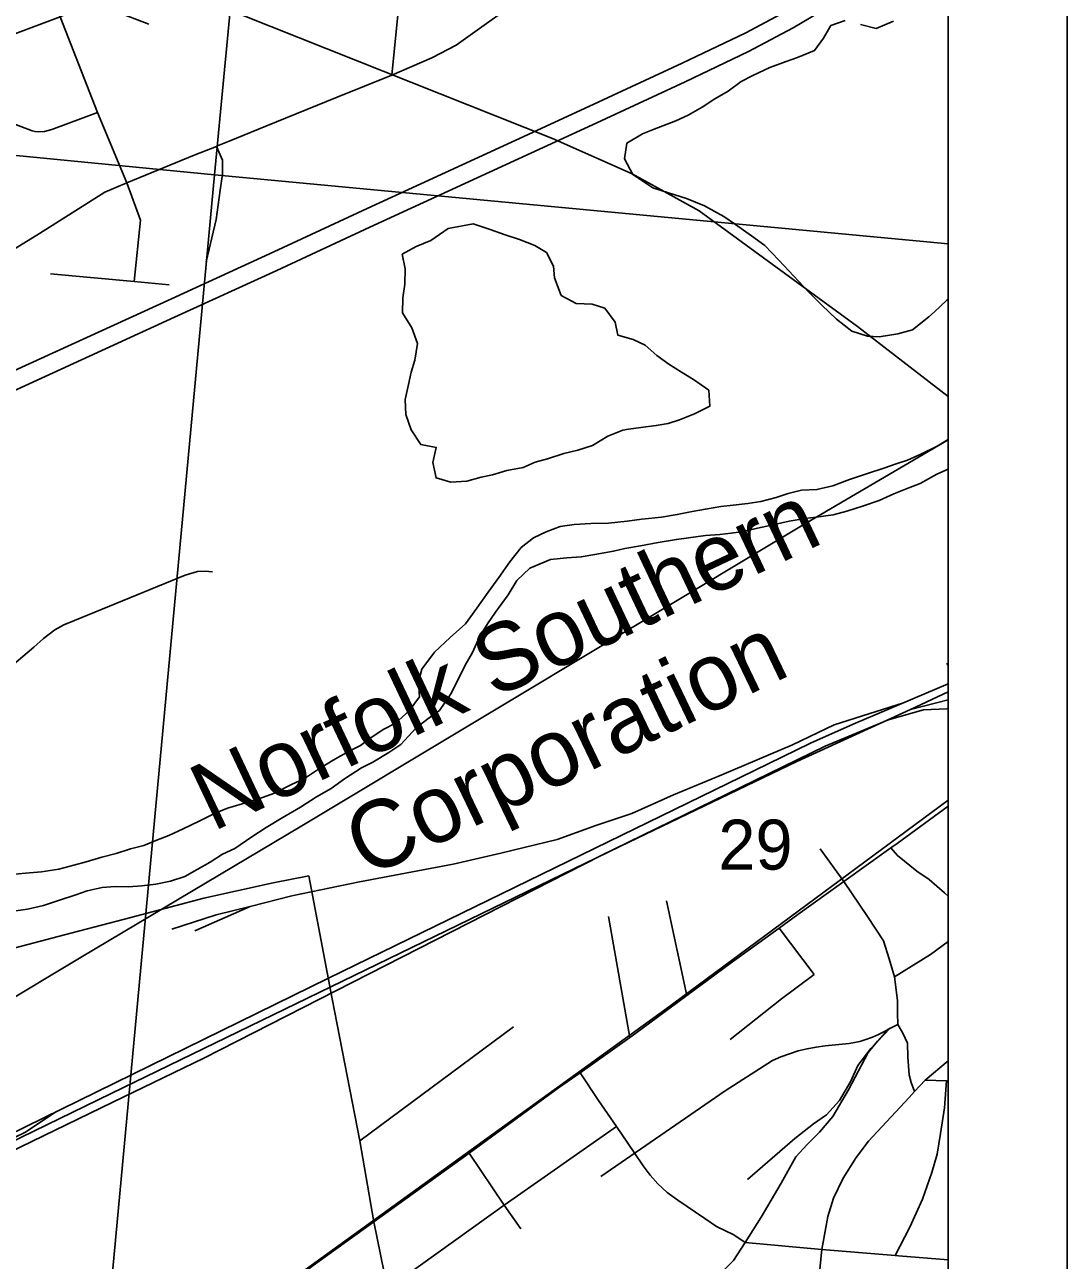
# Model space of a CAD drawing. Extents: x 0 to 34, y 0 to 22.
# Drawn here: x 8.126 to 9, y 18.996 to 20.032 of the extents above; entities that cross this region are included whole.
import ezdxf

# ---------------------------------------------------------------- set-up
doc = ezdxf.new("R2010")
doc.units = 0
for name, color, linetype in [('Default', 7, 'Continuous'), ('GM_X_City_Street', 7, 'Continuous'), ('GM_X_Major_River', 7, 'Continuous'), ('GM_X_Minor_Lake', 7, 'Continuous'), ('GM_X_Rail_Line', 7, 'Continuous'), ('GM_X_Rail_Line_Text', 7, 'Continuous'), ('GM_X_Section', 7, 'Continuous'), ('GM_X_Section_Text', 7, 'Continuous'), ('GM_X_State_Route', 7, 'Continuous'), ('GM_X_Township_Road', 7, 'Continuous'), ('SH_Data', 7, 'Continuous')]:
    doc.layers.add(name, color=color, linetype=linetype)

msp = doc.modelspace()

# ---------------------------------------------------------------- linework, layer by layer
at = {"layer": 'Default'}
for points in [[(8.3798, 20.9), (7.5759, 20.9), (7.374, 20.8667), (7.2927, 20.0028), (8.285, 19.9059)], [(8.5153, 20.9), (8.3798, 20.9), (8.285, 19.9059), (8.9, 19.8482), (8.9, 20.8606)], [(8.9, 18.837), (8.9, 19.8482), (8.285, 19.9059), (8.1916, 18.9018)]]:
    msp.add_lwpolyline(points, close=True, dxfattribs=at)
at = {"layer": 'GM_X_City_Street'}
for p, q in [((8.9, 19.4944), (8.8991, 19.4967)), ((8.8126, 19.3137), (8.7928, 19.3412)), ((8.681, 19.2181), (8.6638, 19.2976)), ((8.6331, 19.1831), (8.6152, 19.2843)), ((8.7878, 19.2359), (8.7585, 19.2747)), ((8.4068, 19.0963), (8.5355, 19.1919)), ((8.8586, 19), (8.9, 18.9965))]:
    msp.add_line(p, q, dxfattribs=at)
for points in [[(8.4335, 19.9895), (8.441, 20.0627), (8.4729, 20.384)], [(8.2175, 19.8166), (8.2228, 19.8681), (8.2114, 19.8993), (8.1869, 19.9583), (8.1556, 20.0384), (8.1501, 20.0532), (8.1335, 20.0707), (8.1096, 20.0817), (8.0342, 20.1092)], [(7.9945, 19.8742), (8.0527, 19.9846), (8.0579, 19.9917), (8.0631, 19.9974), (8.0717, 20.0041), (8.0993, 20.0174), (8.1556, 20.0384), (8.1779, 20.0488), (8.1864, 20.0488), (8.1969, 20.045), (8.2298, 20.0322)], [(8.2874, 19.9302), (8.2973, 19.9342), (8.3281, 19.9467), (8.3879, 19.9711), (8.4335, 19.9895), (8.4672, 20.004), (8.4875, 20.0146), (8.5131, 20.0328), (8.5273, 20.043), (8.5305, 20.0454)], [(8.1131, 19.9503), (8.132, 19.9428), (8.1345, 19.9423), (8.137, 19.942), (8.1423, 19.9423), (8.1485, 19.944), (8.1869, 19.9583)], [(7.7618, 19.5806), (7.802, 19.6195), (7.8359, 19.6562), (7.8639, 19.6856), (7.931, 19.7299), (7.9806, 19.7598), (7.9848, 19.7624), (8.0304, 19.7914), (8.0395, 19.797), (8.0847, 19.8242), (8.1383, 19.8568), (8.193, 19.8914), (8.2114, 19.8993), (8.268, 19.9224), (8.2865, 19.9299), (8.2874, 19.9302)], [(8.2779, 19.8331), (8.2863, 19.8687), (8.2897, 19.8933), (8.2915, 19.9067), (8.2915, 19.9182), (8.2865, 19.9299)], [(8.1473, 19.823), (8.2175, 19.8166), (8.2469, 19.8139)], [(7.9868, 19.4559), (8.0714, 19.4746), (8.0891, 19.4803), (8.0996, 19.485), (8.1089, 19.4904), (8.1186, 19.4976), (8.1333, 19.5101), (8.1416, 19.5173), (8.1511, 19.5247), (8.1587, 19.5289), (8.1676, 19.5326), (8.2603, 19.5706), (8.2708, 19.5735), (8.277, 19.5739), (8.2833, 19.5733)], [(8.5914, 19.1535), (8.6331, 19.1831), (8.6383, 19.1867), (8.681, 19.2181), (8.6992, 19.2315), (8.7174, 19.2449), (8.7585, 19.2747), (8.7741, 19.286), (8.8126, 19.3137), (8.8521, 19.3419), (8.8573, 19.3457), (8.9, 19.3769)], [(8.9, 19.3014), (8.897, 19.3043), (8.8843, 19.3155), (8.8738, 19.3224), (8.8576, 19.3354), (8.8521, 19.3419)], [(8.0347, 19.2363), (8.1645, 19.2704), (8.2095, 19.2823), (8.2434, 19.291), (8.276, 19.2997), (8.3342, 19.3126), (8.3641, 19.3185)], [(8.4355, 18.9398), (8.4299, 18.9723), (8.4186, 19.0285), (8.4068, 19.0963), (8.3837, 19.2155), (8.3641, 19.3185)], [(8.8577, 19.2035), (8.8576, 19.2139), (8.855, 19.2338), (8.8507, 19.249), (8.846, 19.2639), (8.8326, 19.2845), (8.8126, 19.3137)], [(8.855, 19.2338), (8.8854, 19.2525), (8.9, 19.2634)], [(8.7172, 19.1814), (8.7603, 19.2155), (8.7878, 19.2359)], [(8.872, 19.1378), (8.8692, 19.1453), (8.8675, 19.1516), (8.8663, 19.1666), (8.866, 19.1783), (8.8621, 19.1865), (8.8578, 19.194), (8.8577, 19.2035)], [(8.73, 19.0112), (8.7432, 19.0324), (8.76, 19.061), (8.7723, 19.0831), (8.7818, 19.0933), (8.7922, 19.1035), (8.8034, 19.1169), (8.8165, 19.1392), (8.833, 19.1703), (8.8408, 19.18), (8.8495, 19.1897), (8.8578, 19.194)], [(8.8673, 19.1327), (8.872, 19.1378), (8.8808, 19.1472), (8.9, 19.1634)], [(8.2002, 18.8698), (8.2471, 18.9042), (8.2897, 18.9356), (8.3581, 18.985), (8.3706, 18.994), (8.4186, 19.0285), (8.4985, 19.0861), (8.5735, 19.1408), (8.5914, 19.1535)], [(8.5914, 19.1535), (8.6068, 19.1301), (8.6219, 19.1083), (8.6369, 19.0865), (8.6443, 19.0755), (8.6502, 19.0677), (8.6566, 19.0603), (8.6644, 19.0532), (8.6734, 19.0467), (8.6961, 19.0312), (8.7058, 19.0247), (8.7203, 19.0176), (8.73, 19.0112)], [(8.8556, 19.0002), (8.868, 19.0241), (8.8787, 19.0476), (8.8863, 19.0698), (8.891, 19.0851), (8.8936, 19.1026), (8.897, 19.124), (8.8987, 19.1466)], [(8.8808, 19.1472), (8.8987, 19.1466), (8.9, 19.1465)], [(8.7943, 19.0053), (8.7992, 19.0329), (8.804, 19.0483), (8.8121, 19.065), (8.8231, 19.0823), (8.8332, 19.0962), (8.8673, 19.1327)], [(8.4299, 18.9723), (8.5279, 19.0424), (8.6219, 19.1083)], [(8.5419, 19.0225), (8.5279, 19.0424), (8.4985, 19.0861)], [(8.4355, 18.9398), (8.4476, 18.9405), (8.4539, 18.9407), (8.4594, 18.9403), (8.4657, 18.9393), (8.4707, 18.9384), (8.4768, 18.9376), (8.4833, 18.9372), (8.5028, 18.9374), (8.5692, 18.9412), (8.6354, 18.9461), (8.6447, 18.9469), (8.6501, 18.9479), (8.6571, 18.9493), (8.6663, 18.9519), (8.6765, 18.9569), (8.6889, 18.9654), (8.6987, 18.9742), (8.7201, 18.996), (8.73, 19.0112)], [(8.73, 19.0112), (8.7943, 19.0053), (8.8556, 19.0002), (8.8586, 19)], [(8.7706, 18.7597), (8.7797, 18.8608), (8.7943, 19.0053)]]:
    msp.add_lwpolyline(points, dxfattribs=at)
at = {"layer": 'GM_X_Major_River'}
for points in [[(8.9, 19.6841), (8.891, 19.6785), (8.8772, 19.672), (8.8661, 19.6669), (8.8565, 19.6637), (8.8462, 19.6601), (8.8324, 19.6558), (8.8175, 19.6508), (8.8033, 19.6454), (8.79, 19.6422), (8.777, 19.6417), (8.766, 19.6389), (8.756, 19.6357), (8.743, 19.6322), (8.732, 19.6305), (8.7198, 19.6292), (8.7095, 19.6279), (8.6966, 19.6259), (8.6855, 19.6238), (8.6729, 19.6214), (8.6596, 19.619), (8.6432, 19.6175), (8.631, 19.6158), (8.6154, 19.6142), (8.6006, 19.6138), (8.5865, 19.6129), (8.5747, 19.6113), (8.5629, 19.6069), (8.5525, 19.6018), (8.5421, 19.5937), (8.5327, 19.5817), (8.5234, 19.5686), (8.5144, 19.5562), (8.505, 19.5428), (8.4953, 19.5297), (8.4825, 19.5181), (8.4693, 19.5059), (8.4588, 19.4916), (8.4559, 19.4811), (8.4568, 19.4685), (8.4482, 19.4569), (8.4366, 19.4465), (8.427, 19.4414), (8.417, 19.4351), (8.4074, 19.4277), (8.3974, 19.4226), (8.3844, 19.4153), (8.3721, 19.4079), (8.3605, 19.4002), (8.3494, 19.3951), (8.3352, 19.3878), (8.3252, 19.3842), (8.313, 19.3802), (8.2958, 19.3753), (8.2855, 19.3709), (8.2721, 19.3644), (8.2586, 19.3578)], [(8.642, 19.5951), (8.6569, 19.5978), (8.6722, 19.6005), (8.6824, 19.6018), (8.6965, 19.6038), (8.7087, 19.6047), (8.7182, 19.6057), (8.7285, 19.607), (8.7403, 19.6098), (8.7544, 19.6129), (8.7667, 19.6157), (8.78, 19.6181), (8.7895, 19.619), (8.8036, 19.621), (8.8151, 19.6242), (8.8292, 19.6285), (8.8422, 19.6332), (8.8545, 19.6386), (8.8671, 19.6437), (8.8767, 19.6473), (8.8905, 19.655), (8.9, 19.6592)], [(8.1182, 19.2892), (8.1281, 19.2905), (8.1415, 19.2937), (8.1534, 19.2976), (8.1687, 19.3026), (8.1782, 19.3059), (8.1908, 19.3086), (8.2015, 19.3096), (8.2128, 19.3093), (8.2239, 19.3102), (8.2357, 19.3115), (8.2479, 19.3139), (8.2601, 19.3179), (8.2705, 19.3237), (8.2813, 19.33), (8.2916, 19.3366), (8.302, 19.3413), (8.3162, 19.3513), (8.3282, 19.359), (8.3416, 19.3671), (8.357, 19.3759), (8.3705, 19.3848), (8.3828, 19.3917), (8.3939, 19.3999), (8.4082, 19.4091), (8.4178, 19.4138), (8.4312, 19.4219), (8.4412, 19.4286), (8.454, 19.4424), (8.4637, 19.4501), (8.4737, 19.4571), (8.4831, 19.471), (8.4886, 19.4819), (8.495, 19.4951), (8.5012, 19.5056), (8.5072, 19.5188), (8.5139, 19.5297), (8.5205, 19.5394), (8.5311, 19.554), (8.5385, 19.566), (8.5494, 19.5764), (8.5666, 19.5837), (8.5803, 19.5849), (8.5925, 19.5858), (8.6039, 19.5879), (8.6195, 19.5906), (8.6291, 19.5927), (8.642, 19.5951)], [(8.2586, 19.3578), (8.2467, 19.3523), (8.2356, 19.348), (8.2257, 19.344), (8.2146, 19.3412), (8.2024, 19.3373), (8.1905, 19.3341), (8.1772, 19.3302), (8.1669, 19.3274), (8.1543, 19.3242), (8.1398, 19.3218), (8.1265, 19.3206), (8.1147, 19.3197)]]:
    msp.add_lwpolyline(points, dxfattribs=at)
at = {"layer": 'GM_X_Minor_Lake'}
for points in [[(8.8137, 20.0354), (8.8018, 20.0311), (8.7955, 20.0205), (8.7881, 20.0101), (8.7739, 20.0043), (8.7644, 20.001), (8.7506, 19.996), (8.7364, 19.9894), (8.7264, 19.9843), (8.7156, 19.9762), (8.7045, 19.9696), (8.6937, 19.9626), (8.6822, 19.956), (8.6718, 19.9512), (8.6535, 19.9444), (8.6439, 19.9404), (8.6308, 19.9327), (8.6287, 19.9194), (8.6356, 19.9064), (8.6525, 19.895), (8.6657, 19.891), (8.6808, 19.8861), (8.6959, 19.8801), (8.712, 19.871), (8.7218, 19.8644), (8.7353, 19.855), (8.7465, 19.8468)], [(8.8543, 20.0349), (8.8398, 20.0288), (8.8265, 20.0321)], [(8.6272, 19.6919), (8.6322, 19.6929), (8.6425, 19.6942), (8.6554, 19.6959), (8.6653, 19.6976), (8.6749, 19.7008), (8.6875, 19.7058), (8.7002, 19.712), (8.6993, 19.7254), (8.6866, 19.7344), (8.6764, 19.7407), (8.6659, 19.7473), (8.6558, 19.7547), (8.6461, 19.7633), (8.6359, 19.7681), (8.6231, 19.7717), (8.621, 19.7824), (8.6122, 19.7944), (8.6016, 19.7976), (8.5883, 19.7983), (8.5755, 19.805), (8.5701, 19.8196), (8.5692, 19.8295), (8.5633, 19.841), (8.5535, 19.8469), (8.5407, 19.8517), (8.5286, 19.8557), (8.5162, 19.8602), (8.5019, 19.865), (8.4809, 19.8609)], [(8.4809, 19.8609), (8.4663, 19.8511), (8.4541, 19.846), (8.4422, 19.8394), (8.4447, 19.8272), (8.4445, 19.8143), (8.4428, 19.8029), (8.4426, 19.7904), (8.4503, 19.7777), (8.4551, 19.7647), (8.4529, 19.7507), (8.4497, 19.7405), (8.4477, 19.7303), (8.4448, 19.7178), (8.4454, 19.7052), (8.4497, 19.6922), (8.4579, 19.68), (8.4708, 19.6775), (8.4679, 19.665), (8.4707, 19.652), (8.4832, 19.6484), (8.4965, 19.6493), (8.5084, 19.6526), (8.5179, 19.6547), (8.5301, 19.6583), (8.5438, 19.6607), (8.5538, 19.6651), (8.5641, 19.668), (8.5779, 19.6724), (8.5897, 19.6752), (8.6019, 19.6792), (8.6146, 19.687), (8.6272, 19.6919)], [(8.7465, 19.8468), (8.758, 19.8344), (8.7707, 19.8212), (8.7834, 19.8076), (8.7942, 19.7968), (8.8065, 19.7851), (8.8192, 19.775), (8.8324, 19.7709), (8.8423, 19.7703), (8.8579, 19.7727), (8.8701, 19.7762), (8.884, 19.787)], [(8.884, 19.787), (8.8886, 19.7911), (8.8991, 19.8011), (8.9, 19.8018)]]:
    msp.add_lwpolyline(points, dxfattribs=at)
at = {"layer": 'GM_X_Rail_Line'}
for p, q in [((8.8684, 19.458), (8.9, 19.4728)), ((8.8684, 19.458), (8.9, 19.4661)), ((8.3149, 19.2929), (8.2684, 19.2725)), ((8.0047, 19.0346), (8.1997, 19.1287))]:
    msp.add_line(p, q, dxfattribs=at)
for points in [[(8.9, 19.7201), (8.8241, 19.7789), (8.6912, 19.8758), (8.6351, 19.9068), (8.5683, 19.9364), (8.0479, 20.1435), (7.7234, 20.2719), (7.6413, 20.3112), (7.5745, 20.3497), (7.5124, 20.3999), (7.4389, 20.4669), (7.3202, 20.5714), (7.2541, 20.6262), (7.22, 20.6622), (7.1932, 20.71), (7.1775, 20.7509), (7.1663, 20.8011)], [(8.1732, 19.2502), (8.3581, 19.3603), (8.777, 19.6117), (8.9, 19.6838)], [(8.0663, 19.0788), (8.3806, 19.2326), (8.7378, 19.4067), (8.7846, 19.4298), (8.8205, 19.4456), (8.9, 19.4793)], [(8.8627, 19.4635), (8.8046, 19.4451), (8.7695, 19.4283), (8.7104, 19.4032), (8.6699, 19.3864), (8.6349, 19.3706), (8.6048, 19.3607), (8.5723, 19.3489), (8.5249, 19.3376), (8.485, 19.3282), (8.4065, 19.3134), (8.3498, 19.3016), (8.3149, 19.2929)], [(7.315, 18.7406), (7.3985, 18.7687), (7.485, 18.7978), (7.5613, 18.829), (7.7648, 18.9251), (8.1982, 19.1361), (8.6248, 19.3431), (8.7733, 19.4142), (8.8684, 19.458)], [(8.1997, 19.1287), (8.276, 19.1656), (8.6085, 19.3352), (8.7969, 19.4273), (8.8474, 19.4482), (8.8502, 19.4492), (8.8529, 19.4501), (8.8794, 19.4575), (8.8989, 19.4585), (8.9, 19.4586)], [(7.6668, 18.5653), (8.1158, 18.8165), (8.1934, 18.8674), (8.6624, 19.2063), (8.9, 19.382)], [(8.3149, 19.2929), (8.2862, 19.2858), (8.2492, 19.2739)], [(7.342, 18.7562), (7.4219, 18.8021), (7.603, 18.9154), (7.8838, 19.0818), (8.0994, 19.2062), (8.1732, 19.2502)], [(8.8516, 19.1907), (8.8468, 19.1879), (8.8418, 19.1855), (8.8367, 19.1834), (8.8302, 19.181), (8.8259, 19.1797), (8.8215, 19.1787), (8.817, 19.178), (8.7969, 19.176), (8.7893, 19.175), (8.7818, 19.1735), (8.7744, 19.1717), (8.7671, 19.1694), (8.7599, 19.1667), (8.7529, 19.1637), (8.713, 19.1383), (8.6088, 19.0666)], [(8.8516, 19.1907), (8.8354, 19.1737), (8.8245, 19.1596), (8.8186, 19.1464), (8.8091, 19.1303), (8.7982, 19.1182), (8.7871, 19.1106), (8.7716, 19.0984), (8.7318, 19.0639)], [(8.1525, 19.121), (8.1259, 19.1034), (8.0162, 19.0506), (7.8155, 18.9528), (7.7483, 18.9204), (7.6912, 18.8931), (7.5659, 18.8318), (7.522, 18.8129), (7.4953, 18.802), (7.4604, 18.7902), (7.4221, 18.7782), (7.3945, 18.773)]]:
    msp.add_lwpolyline(points, dxfattribs=at)
at = {"layer": 'GM_X_Section'}
msp.add_lwpolyline([(7.2927, 20.0028), (8.285, 19.9059), (8.1916, 18.9018), (7.1919, 18.9909)], close=True, dxfattribs=at)
at = {"layer": 'GM_X_State_Route'}
for points in [[(8.9, 15.5977), (8.9, 20.2522)], [(7.9145, 19.6017), (7.919, 19.6059), (7.9241, 19.6107), (7.9417, 19.6273), (7.9543, 19.6377), (7.9749, 19.6558), (8.0162, 19.6844), (8.0525, 19.7071), (8.0818, 19.7236), (8.1167, 19.7417), (8.2489, 19.8022), (8.3348, 19.8415), (8.4128, 19.8779), (8.5478, 19.9399), (8.6031, 19.9652), (8.6771, 19.9996), (8.7304, 20.0251), (8.7676, 20.045), (8.8026, 20.0656), (8.8278, 20.0809), (8.8523, 20.0963), (8.8923, 20.1205), (8.9, 20.1252)], [(7.9106, 19.5771), (7.9155, 19.5822), (7.9274, 19.5935), (7.9326, 19.5984), (7.9502, 19.615), (7.9628, 19.6253), (7.9834, 19.6435), (8.0247, 19.6721), (8.055, 19.6915), (8.0842, 19.7079), (8.1191, 19.726), (8.2514, 19.7866), (8.3372, 19.8259), (8.4152, 19.8622), (8.5502, 19.9242), (8.6055, 19.9496), (8.6795, 19.9839), (8.7328, 20.0094), (8.77, 20.0293), (8.8051, 20.0499), (8.8302, 20.0652), (8.8547, 20.0807), (8.8947, 20.1049), (8.9, 20.1081)]]:
    msp.add_lwpolyline(points, dxfattribs=at)
at = {"layer": 'GM_X_Township_Road'}
msp.add_lwpolyline([(8.9, 14.1), (8.9, 20.9)], dxfattribs=at)
at = {"layer": 'SH_Data'}
for p, q in [((9, 21), (9, 14)), ((8.9, 20.9), (8.9, 14.1))]:
    msp.add_line(p, q, dxfattribs=at)

# ---------------------------------------------------------------- texts
at = {"layer": 'GM_X_Rail_Line_Text'}
for s, rotation, p in [('Norfolk Southern', 25.3173, (8.2833, 19.3551)), ('Corporation', 25.6236, (8.4126, 19.3163))]:
    msp.add_text(s, height=0.056629, rotation=rotation, dxfattribs=at).set_placement(p)
at = {"layer": 'GM_X_Section_Text'}
msp.add_text('29', height=0.04186, rotation=0, dxfattribs=at).set_placement((8.7074, 19.3237))

doc.saveas('drawing.dxf')
